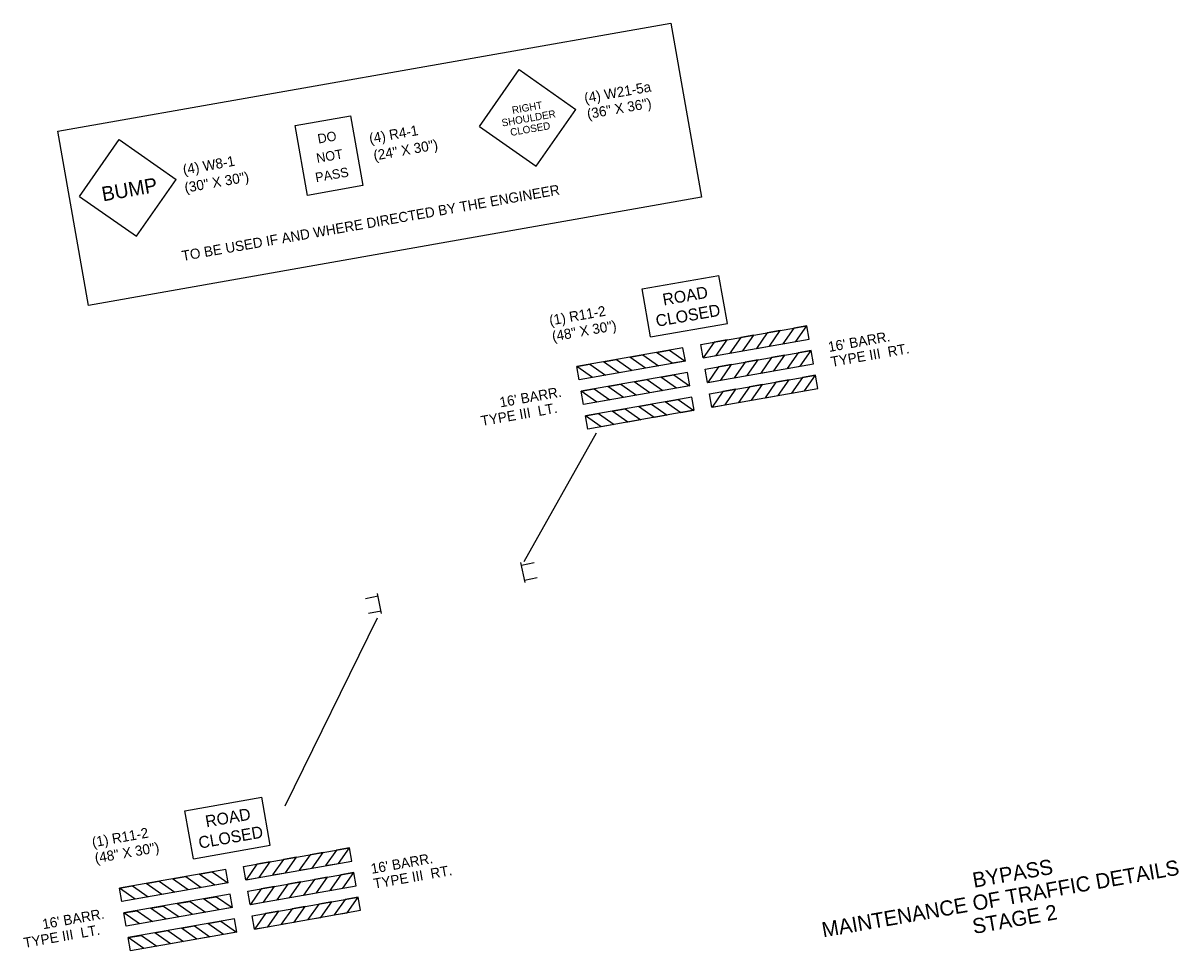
# Model space of a CAD drawing. Extents: x 986385 to 987873, y 1837463 to 1838653.
# Drawn here: x 987186 to 987873, y 1837639 to 1838190 of the extents above; entities that cross this region are included whole.
import ezdxf

# ---------------------------------------------------------------- set-up
doc = ezdxf.new("R2010")
doc.units = 0
for name, color, linetype in [('3', 7, 'Continuous'), ('60', 7, 'Continuous'), ('8', 7, 'Continuous'), ('C-ANNO-DIMS', 7, 'Continuous'), ('Level 43', 7, 'Continuous'), ('Level 8', 7, 'Continuous'), ('R_Draft', 7, 'Continuous')]:
    doc.layers.add(name, color=color, linetype=linetype)

msp = doc.modelspace()

# ---------------------------------------------------------------- linework, layer by layer
at = {"layer": '3'}
for p, q in [((987553.99, 1838032.51), (987599.64, 1838040.56)), ((987604.66, 1838012.04), (987599.64, 1838040.56)), ((987559.02, 1838004), (987553.99, 1838032.51)), ((987559.02, 1838004), (987604.66, 1838012.04)), ((987588.78, 1837999.45), (987651.84, 1838010.57)), ((987653.23, 1838002.65), (987651.84, 1838010.57)), ((987578.26, 1837997.59), (987515.2, 1837986.47)), ((987579.65, 1837989.67), (987578.26, 1837997.59)), ((987590.17, 1837991.53), (987588.78, 1837999.45)), ((987590.17, 1837991.53), (987653.23, 1838002.65)), ((987653.18, 1838002.66), (987653.22, 1838002.72)), ((987579.65, 1837989.67), (987516.59, 1837978.56)), ((987591.36, 1837984.77), (987654.42, 1837995.89)), ((987655.82, 1837987.99), (987654.42, 1837995.89)), ((987655.82, 1837987.99), (987654.42, 1837995.89)), ((987516.59, 1837978.56), (987515.2, 1837986.47)), ((987580.85, 1837982.91), (987517.79, 1837971.8)), ((987582.24, 1837975.02), (987580.85, 1837982.91)), ((987592.76, 1837976.87), (987591.36, 1837984.77)), ((987592.76, 1837976.87), (987655.82, 1837987.99)), ((987516.64, 1837978.59), (987516.58, 1837978.63)), ((987593.94, 1837970.14), (987657, 1837981.26)), ((987658.4, 1837973.36), (987657, 1837981.26)), ((987519.18, 1837963.9), (987517.79, 1837971.8)), ((987519.18, 1837963.9), (987517.79, 1837971.8)), ((987582.24, 1837975.02), (987519.18, 1837963.9)), ((987595.34, 1837962.24), (987593.94, 1837970.14)), ((987595.34, 1837962.24), (987658.4, 1837973.36)), ((987583.43, 1837968.28), (987520.37, 1837957.17)), ((987584.82, 1837960.39), (987583.43, 1837968.28)), ((987521.76, 1837949.27), (987520.37, 1837957.17)), ((987584.82, 1837960.39), (987521.76, 1837949.27)), ((987484.44, 1837858.08), (987481.98, 1837870)), ((987482.31, 1837868.37), (987489.83, 1837869.92)), ((987484.13, 1837859.58), (987491.65, 1837861.14)), ((987397.09, 1837849.95), (987389.57, 1837848.39)), ((987399.21, 1837839.65), (987396.75, 1837851.57)), ((987398.9, 1837841.16), (987391.38, 1837839.6)), ((987282.32, 1837722.5), (987327.96, 1837730.55)), ((987332.99, 1837702.04), (987327.96, 1837730.55)), ((987287.34, 1837693.99), (987282.32, 1837722.5)), ((987287.34, 1837693.99), (987332.99, 1837702.04)), ((987317.1, 1837689.44), (987380.16, 1837700.56)), ((987381.56, 1837692.64), (987380.16, 1837700.56)), ((987306.58, 1837687.59), (987243.52, 1837676.47)), ((987307.98, 1837679.67), (987306.58, 1837687.59)), ((987318.5, 1837681.52), (987317.1, 1837689.44)), ((987318.5, 1837681.52), (987381.56, 1837692.64)), ((987381.51, 1837692.66), (987381.54, 1837692.71)), ((987319.69, 1837674.76), (987382.75, 1837685.88)), ((987384.14, 1837677.99), (987382.75, 1837685.88)), ((987384.14, 1837677.99), (987382.75, 1837685.88)), ((987244.92, 1837668.55), (987243.52, 1837676.47)), ((987307.98, 1837679.67), (987244.92, 1837668.55)), ((987321.08, 1837666.87), (987319.69, 1837674.76)), ((987321.08, 1837666.87), (987384.14, 1837677.99)), ((987244.96, 1837668.58), (987244.91, 1837668.62)), ((987309.17, 1837672.91), (987246.11, 1837661.79)), ((987310.56, 1837665.01), (987309.17, 1837672.91)), ((987322.27, 1837660.13), (987385.33, 1837671.25)), ((987386.72, 1837663.36), (987385.33, 1837671.25)), ((987247.5, 1837653.89), (987246.11, 1837661.79)), ((987247.5, 1837653.89), (987246.11, 1837661.79)), ((987310.56, 1837665.01), (987247.5, 1837653.89)), ((987323.66, 1837652.24), (987322.27, 1837660.13)), ((987323.66, 1837652.24), (987386.72, 1837663.36)), ((987311.75, 1837658.28), (987248.69, 1837647.16)), ((987313.14, 1837650.38), (987311.75, 1837658.28)), ((987250.08, 1837639.26), (987248.69, 1837647.16)), ((987313.14, 1837650.38), (987250.08, 1837639.26))]:
    msp.add_line(p, q, dxfattribs=at)
for points in [[(987651.84, 1838010.57), (987644.09, 1838009.18), (987637.6, 1837999.92), (987645.33, 1838001.28)], [(987620.32, 1838005.01), (987612.57, 1838003.62), (987606.09, 1837994.36), (987613.82, 1837995.72)], [(987636.08, 1838007.79), (987628.33, 1838006.4), (987621.85, 1837997.14), (987629.58, 1837998.5)], [(987604.56, 1838002.23), (987596.82, 1838000.84), (987590.33, 1837991.58), (987598.06, 1837992.94)], [(987530.96, 1837989.25), (987538.71, 1837990.59), (987547.97, 1837984.11), (987540.24, 1837982.75)], [(987546.71, 1837992.03), (987554.47, 1837993.37), (987563.73, 1837986.89), (987556, 1837985.53)], [(987562.47, 1837994.81), (987570.23, 1837996.15), (987579.48, 1837989.67), (987571.76, 1837988.31)], [(987622.91, 1837990.33), (987615.16, 1837988.94), (987608.68, 1837979.68), (987616.41, 1837981.05)], [(987638.67, 1837993.11), (987630.92, 1837991.72), (987624.44, 1837982.46), (987632.16, 1837983.82)], [(987654.42, 1837995.89), (987646.68, 1837994.5), (987640.19, 1837985.24), (987647.92, 1837986.6)], [(987515.2, 1837986.47), (987522.96, 1837987.82), (987532.21, 1837981.33), (987524.48, 1837979.97)], [(987607.15, 1837987.55), (987599.4, 1837986.16), (987592.92, 1837976.9), (987600.65, 1837978.27)], [(987549.3, 1837977.35), (987557.06, 1837978.7), (987566.32, 1837972.21), (987558.59, 1837970.85)], [(987565.06, 1837980.13), (987572.81, 1837981.47), (987582.07, 1837974.99), (987574.34, 1837973.63)], [(987641.25, 1837978.48), (987633.5, 1837977.09), (987627.02, 1837967.83), (987634.74, 1837969.19)], [(987657, 1837981.26), (987649.26, 1837979.87), (987642.77, 1837970.61), (987650.5, 1837971.97)], [(987517.79, 1837971.8), (987525.54, 1837973.14), (987534.8, 1837966.66), (987527.07, 1837965.29)], [(987533.54, 1837974.57), (987541.3, 1837975.92), (987550.56, 1837969.43), (987542.83, 1837968.07)], [(987609.73, 1837972.92), (987601.98, 1837971.53), (987595.5, 1837962.27), (987603.23, 1837963.64)], [(987625.49, 1837975.7), (987617.74, 1837974.31), (987611.26, 1837965.05), (987618.99, 1837966.41)], [(987551.88, 1837962.72), (987559.64, 1837964.07), (987568.9, 1837957.58), (987561.17, 1837956.22)], [(987567.64, 1837965.5), (987575.39, 1837966.84), (987584.65, 1837960.36), (987576.92, 1837959)], [(987520.37, 1837957.17), (987528.12, 1837958.51), (987537.38, 1837952.03), (987529.65, 1837950.66)], [(987536.12, 1837959.94), (987543.88, 1837961.29), (987553.14, 1837954.8), (987545.41, 1837953.44)], [(987348.65, 1837695), (987340.9, 1837693.61), (987334.42, 1837684.35), (987342.14, 1837685.72)], [(987364.4, 1837697.78), (987356.66, 1837696.39), (987350.17, 1837687.13), (987357.9, 1837688.49)], [(987380.16, 1837700.56), (987372.41, 1837699.17), (987365.93, 1837689.91), (987373.66, 1837691.27)], [(987332.89, 1837692.22), (987325.14, 1837690.83), (987318.66, 1837681.57), (987326.39, 1837682.94)], [(987275.04, 1837682.02), (987282.79, 1837683.37), (987292.05, 1837676.88), (987284.32, 1837675.52)], [(987290.79, 1837684.8), (987298.55, 1837686.14), (987307.81, 1837679.66), (987300.08, 1837678.3)], [(987366.99, 1837683.1), (987359.24, 1837681.71), (987352.76, 1837672.45), (987360.49, 1837673.82)], [(987382.75, 1837685.88), (987375, 1837684.49), (987368.52, 1837675.23), (987376.25, 1837676.6)], [(987243.52, 1837676.47), (987251.28, 1837677.81), (987260.54, 1837671.33), (987252.81, 1837669.96)], [(987259.28, 1837679.24), (987267.04, 1837680.59), (987276.3, 1837674.11), (987268.57, 1837672.74)], [(987335.48, 1837677.55), (987327.73, 1837676.16), (987321.25, 1837666.9), (987328.98, 1837668.26)], [(987351.23, 1837680.32), (987343.49, 1837678.93), (987337, 1837669.68), (987344.73, 1837671.04)], [(987277.63, 1837667.35), (987285.38, 1837668.69), (987294.64, 1837662.21), (987286.91, 1837660.84)], [(987293.38, 1837670.12), (987301.14, 1837671.47), (987310.4, 1837664.98), (987302.67, 1837663.62)], [(987369.57, 1837668.47), (987361.82, 1837667.08), (987355.34, 1837657.82), (987363.07, 1837659.19)], [(987385.33, 1837671.25), (987377.58, 1837669.86), (987371.1, 1837660.6), (987378.83, 1837661.96)], [(987246.11, 1837661.79), (987253.87, 1837663.13), (987263.13, 1837656.65), (987255.4, 1837655.29)], [(987261.87, 1837664.57), (987269.63, 1837665.91), (987278.88, 1837659.43), (987271.15, 1837658.06)], [(987338.06, 1837662.92), (987330.31, 1837661.53), (987323.83, 1837652.27), (987331.56, 1837653.63)], [(987353.81, 1837665.69), (987346.07, 1837664.3), (987339.58, 1837655.05), (987347.31, 1837656.41)], [(987280.21, 1837652.72), (987287.96, 1837654.06), (987297.22, 1837647.58), (987289.49, 1837646.21)], [(987295.96, 1837655.49), (987303.72, 1837656.84), (987312.98, 1837650.35), (987305.25, 1837648.99)], [(987248.69, 1837647.16), (987256.45, 1837648.5), (987265.71, 1837642.02), (987257.98, 1837640.66)], [(987264.45, 1837649.94), (987272.21, 1837651.28), (987281.46, 1837644.8), (987273.73, 1837643.43)]]:
    msp.add_lwpolyline(points, close=True, dxfattribs=at)
at = {"layer": 'C-ANNO-DIMS'}
for p, q in [((987526.68, 1837946.92), (987483.61, 1837870.29)), ((987396.63, 1837836.96), (987341.69, 1837725.15))]:
    msp.add_line(p, q, dxfattribs=at)
at = {"layer": 'Level 8'}
for p, q in [((987457.29, 1838129.05), (987480.93, 1838162.81)), ((987480.93, 1838162.81), (987514.69, 1838139.17)), ((987491.05, 1838105.41), (987514.69, 1838139.17)), ((987457.29, 1838129.05), (987491.05, 1838105.41)), ((987219.72, 1838087.45), (987243.36, 1838121.21)), ((987243.36, 1838121.21), (987277.12, 1838097.57)), ((987253.48, 1838063.81), (987277.12, 1838097.57)), ((987219.72, 1838087.45), (987253.48, 1838063.81))]:
    msp.add_line(p, q, dxfattribs=at)
msp.add_lwpolyline([(987380.79, 1838135.3), (987388.09, 1838093.89), (987355.23, 1838088.09), (987347.93, 1838129.5)], close=True, dxfattribs=at)
at = {"layer": 'R_Draft'}
msp.add_lwpolyline([(987206.74, 1838126.17), (987571.12, 1838190.42), (987589.35, 1838087.01), (987224.97, 1838022.76)], close=True, dxfattribs=at)

# ---------------------------------------------------------------- texts
at = {"layer": '3'}
for s, height, p in [('ROAD', 7.016, (987566.81, 1838022.61)), ('CLOSED', 7.05, (987562.72, 1838009.96)), ('ROAD', 7.016, (987295.13, 1837712.6)), ('CLOSED', 7.05, (987291.05, 1837699.95))]:
    msp.add_text(s, height=height, rotation=10, dxfattribs=at).set_placement(p)
at = {"layer": '60'}
for s, p in [('MAINTENANCE OF TRAFFIC DETAILS', (987661.6, 1837647.22)), ('BYPASS', (987751.17, 1837676.72)), (' STAGE 2  ', (987747.8, 1837648.71))]:
    msp.add_text(s, height=9, rotation=10, dxfattribs=at).set_placement(p)
at = {"layer": '8'}
for s, p in [('TO BE USED IF AND WHERE DIRECTED BY THE ENGINEER', (987281.04, 1838049.11)), ('(1) R11-2', (987499.36, 1838010.77)), ('(48" X 30")', (987501.02, 1838001.32)), ("16' BARR.", (987665.06, 1837995.03)), ('TYPE III  RT.', (987666.62, 1837986.17)), ("16' BARR.", (987469.84, 1837962.11)), ('TYPE III  LT.', (987458.75, 1837951.01)), ('(1) R11-2', (987227.68, 1837700.77)), ('(48" X 30")', (987229.35, 1837691.31)), ("16' BARR.", (987393.39, 1837685.03)), ('TYPE III  RT.', (987394.95, 1837676.16)), ("16' BARR.", (987198.16, 1837652.1)), ('TYPE III  LT.', (987187.07, 1837641.01))]:
    msp.add_text(s, height=6, rotation=10, dxfattribs=at).set_placement(p)
at = {"layer": 'Level 43'}
for s, height, p in [('RIGHT', 4.369, (987477.06, 1838136.52)), ('SHOULDER', 4.369, (987470.93, 1838128.94)), ('CLOSED', 4.369, (987476.04, 1838123.33)), ('BUMP', 8.629, (987233.7, 1838084.48))]:
    msp.add_text(s, height=height, rotation=10, dxfattribs=at).set_placement(p)
at = {"layer": 'Level 8'}
for s, height, p in [('(4) W21-5a', 6, (987520.15, 1838142.88)), ('(36" X 36")', 6, (987521.81, 1838133.43)), ('(4) R4-1', 6, (987392.38, 1838118.86)), ('DO', 5.597, (987361.69, 1838118.85)), ('(24" X 30")', 6, (987394.93, 1838108.75)), ('NOT', 5.597, (987360.94, 1838107.35)), ('(4) W8-1', 6, (987281.68, 1838100.34)), ('(30" X 30")', 6, (987282.67, 1838089.63)), ('PASS', 5.596, (987360.32, 1838095.87))]:
    msp.add_text(s, height=height, rotation=10, dxfattribs=at).set_placement(p)

doc.saveas('drawing.dxf')
